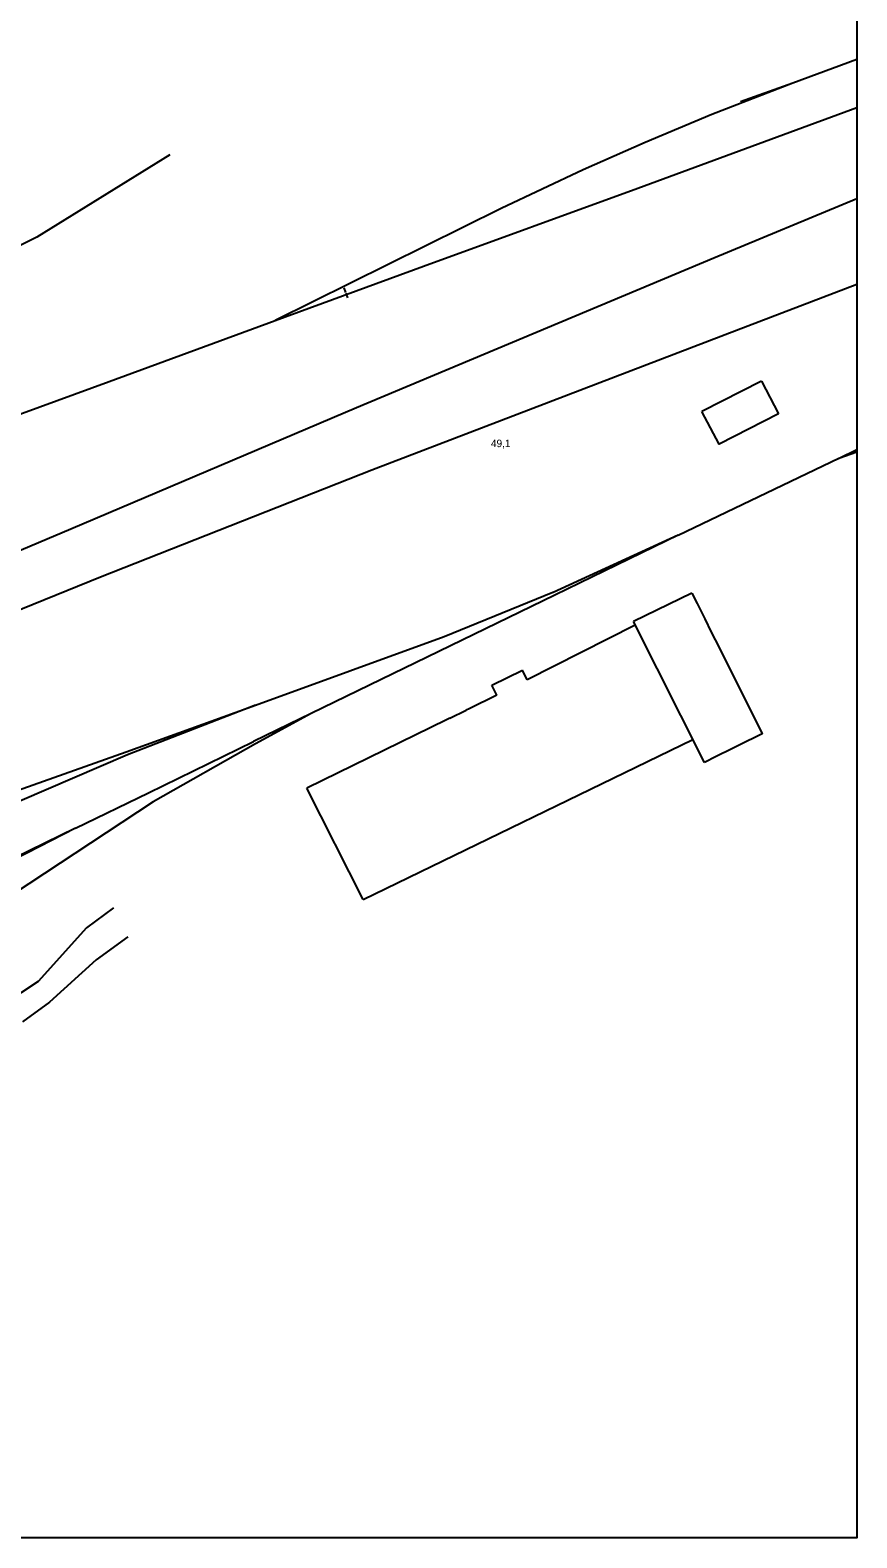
# Model space of a CAD drawing. Extents: x -781661 to -760591, y -1008188 to -975620.
# Drawn here: x -781630.038 to -781628.397, y -1008172.605 to -1008169.611 of the extents above; entities that cross this region are included whole.
import ezdxf

# ---------------------------------------------------------------- set-up
doc = ezdxf.new("R2010")
doc.units = 0
for name, color, linetype in [('Border', 7, 'Continuous'), ('Implicitní', 7, 'Continuous'), ('Koleje_stávající', 7, 'Continuous'), ('Komunikace_stávající', 7, 'Continuous'), ('Objekty_stávající', 7, 'Continuous'), ('SL_05_KOMUNIKACE', 7, 'Continuous')]:
    doc.layers.add(name, color=color, linetype=linetype)

# ---------------------------------------------------------------- blocks, each defined once
blk = doc.blocks.new('5.121_1')
at = {"layer": 'Implicitní'}
blk.add_line((0, 0), (0, 0.005), dxfattribs=at)
blk = doc.blocks.new('přehledka_1')
at = {"layer": 'Border'}
blk.add_lwpolyline([(0, 0), (0.99915, 0), (0.99915, -0.65218), (0, -0.65218)], close=True, dxfattribs=at)
at = {"layer": 'Koleje_stávající'}
for p, q in [((0.98646, -0.3634), (0.97605, -0.36709)), ((0.99551, -0.43788), (0.99915, -0.43611)), ((0.96368, -0.45312), (0.99561, -0.43783))]:
    blk.add_line(p, q, dxfattribs=at)
for points in [[(0.99915, -0.35871), (0.98646, -0.3634), (0.97038, -0.3696), (0.9571, -0.37516), (0.9448, -0.3806), (0.92852, -0.38824), (0.88366, -0.4105)], [(0.70214, -0.47688), (0.73116, -0.46624), (0.75926, -0.45598), (0.79086, -0.44442), (0.82654, -0.43138), (0.85068, -0.4226), (0.88366, -0.4105), (0.91314, -0.39974), (0.9557, -0.38422), (0.9846, -0.37358), (0.99915, -0.36822)], [(0.34457, -0.65218), (0.36094, -0.6463), (0.42022, -0.62434), (0.46232, -0.60838), (0.53854, -0.5786), (0.57568, -0.5638), (0.66464, -0.52712), (0.72204, -0.50292), (0.78868, -0.4748), (0.8431, -0.45184), (0.89984, -0.4278), (0.97074, -0.39804), (0.99915, -0.38627)], [(0.3708, -0.65218), (0.4231, -0.6328), (0.4657, -0.61666), (0.54136, -0.5872), (0.66806, -0.53566), (0.72606, -0.51164), (0.79336, -0.48394), (0.84902, -0.46136), (0.90286, -0.44012), (0.973, -0.41326), (0.99915, -0.40329)], [(0.9956, -0.43784), (0.99915, -0.43657)], [(0.96369, -0.45311), (0.9392, -0.46503), (0.87936, -0.49405)], [(0.96368, -0.45311), (0.93888, -0.46448)], [(0.93882, -0.46451), (0.91721, -0.4733), (0.87973, -0.48691)], [(0.87976, -0.4869), (0.85436, -0.49675), (0.833, -0.50595), (0.7568, -0.54149), (0.69227, -0.57414)], [(0.87973, -0.48691), (0.8541, -0.49617), (0.81712, -0.50929)], [(0.89083, -0.48849), (0.87974, -0.49455), (0.85947, -0.50608), (0.79133, -0.55094)], [(0.84401, -0.51131), (0.85851, -0.50427), (0.87937, -0.49405)], [(0.84401, -0.51131), (0.81958, -0.52321), (0.78416, -0.54033), (0.75967, -0.55229), (0.70542, -0.57871), (0.65749, -0.60528), (0.59036, -0.65218)], [(0.84401, -0.51131), (0.8199, -0.52367), (0.7512, -0.56635), (0.672, -0.61933)]]:
    blk.add_lwpolyline(points, dxfattribs=at)
at = {"layer": 'Komunikace_stávající'}
for points in [[(0.86278, -0.37758), (0.83634, -0.39394), (0.82248, -0.40084), (0.81559, -0.40377), (0.7832, -0.4125), (0.753, -0.42404), (0.7175, -0.43768), (0.67214, -0.4551), (0.6388, -0.4677), (0.63028, -0.47065), (0.6121, -0.47734), (0.56748, -0.49352), (0.52088, -0.51014), (0.49772, -0.51898), (0.48486, -0.5233), (0.47346, -0.527), (0.43028, -0.54132), (0.38862, -0.5539), (0.36736, -0.5607), (0.36645, -0.56105)], [(0.85156, -0.5271), (0.8462, -0.53106), (0.8366, -0.54176), (0.80928, -0.55976)], [(0.85442, -0.53284), (0.8481, -0.53742), (0.83884, -0.54582), (0.83348, -0.54974)]]:
    blk.add_lwpolyline(points, dxfattribs=at)
at = {"layer": 'Objekty_stávající'}
for p, q in [((0.98023, -0.42251), (0.9684, -0.42858)), ((0.98023, -0.42251), (0.98358, -0.42904)), ((0.95514, -0.47099), (0.93372, -0.48183)), ((0.93372, -0.48183), (0.93278, -0.4799)), ((0.92768, -0.48489), (0.9267, -0.48288)), ((0.90116, -0.52546), (0.96662, -0.49367))]:
    blk.add_line(p, q, dxfattribs=at)
for points in [[(0.98358, -0.42904), (0.97184, -0.43506), (0.9684, -0.42858)], [(0.9664, -0.4646), (0.95478, -0.47028)], [(0.9664, -0.4646), (0.96742, -0.46665), (0.96896, -0.46974), (0.97026, -0.47235), (0.9718, -0.47545), (0.973, -0.47785), (0.9745, -0.48087), (0.98034, -0.49258), (0.97953, -0.49298), (0.97644, -0.49451), (0.97431, -0.49556), (0.97124, -0.49707), (0.96892, -0.49822)], [(0.96892, -0.49822), (0.95478, -0.47028)], [(0.9267, -0.48288), (0.93278, -0.4799)], [(0.92768, -0.48489), (0.9222, -0.48757), (0.92157, -0.48788)], [(0.91835, -0.48945), (0.92157, -0.48788)], [(0.91835, -0.48945), (0.91767, -0.48978), (0.88998, -0.50334)], [(0.90116, -0.52546), (0.88998, -0.50334)]]:
    blk.add_lwpolyline(points, dxfattribs=at)
at = {"layer": 'Koleje_stávající', "xscale": 0.2, "yscale": 0.20000000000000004, "rotation": 19.393445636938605}
for p in [(0.8977, -0.40493), (0.89808, -0.40599)]:
    blk.add_blockref('5.121_1', p, dxfattribs=at)
at = {"layer": 'Koleje_stávající'}
blk.add_text('49,1', height=0.0015, dxfattribs=at).set_placement((0.9265, -0.43564))

msp = doc.modelspace()

# ---------------------------------------------------------------- block references
at = {"layer": 'SL_05_KOMUNIKACE', "xscale": 9.999991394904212, "yscale": 9.999991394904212}
msp.add_blockref('přehledka_1', (-781638.3887, -1008166.0829), dxfattribs=at)

doc.saveas('drawing.dxf')
